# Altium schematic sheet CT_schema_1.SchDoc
size 562 x 511 mm
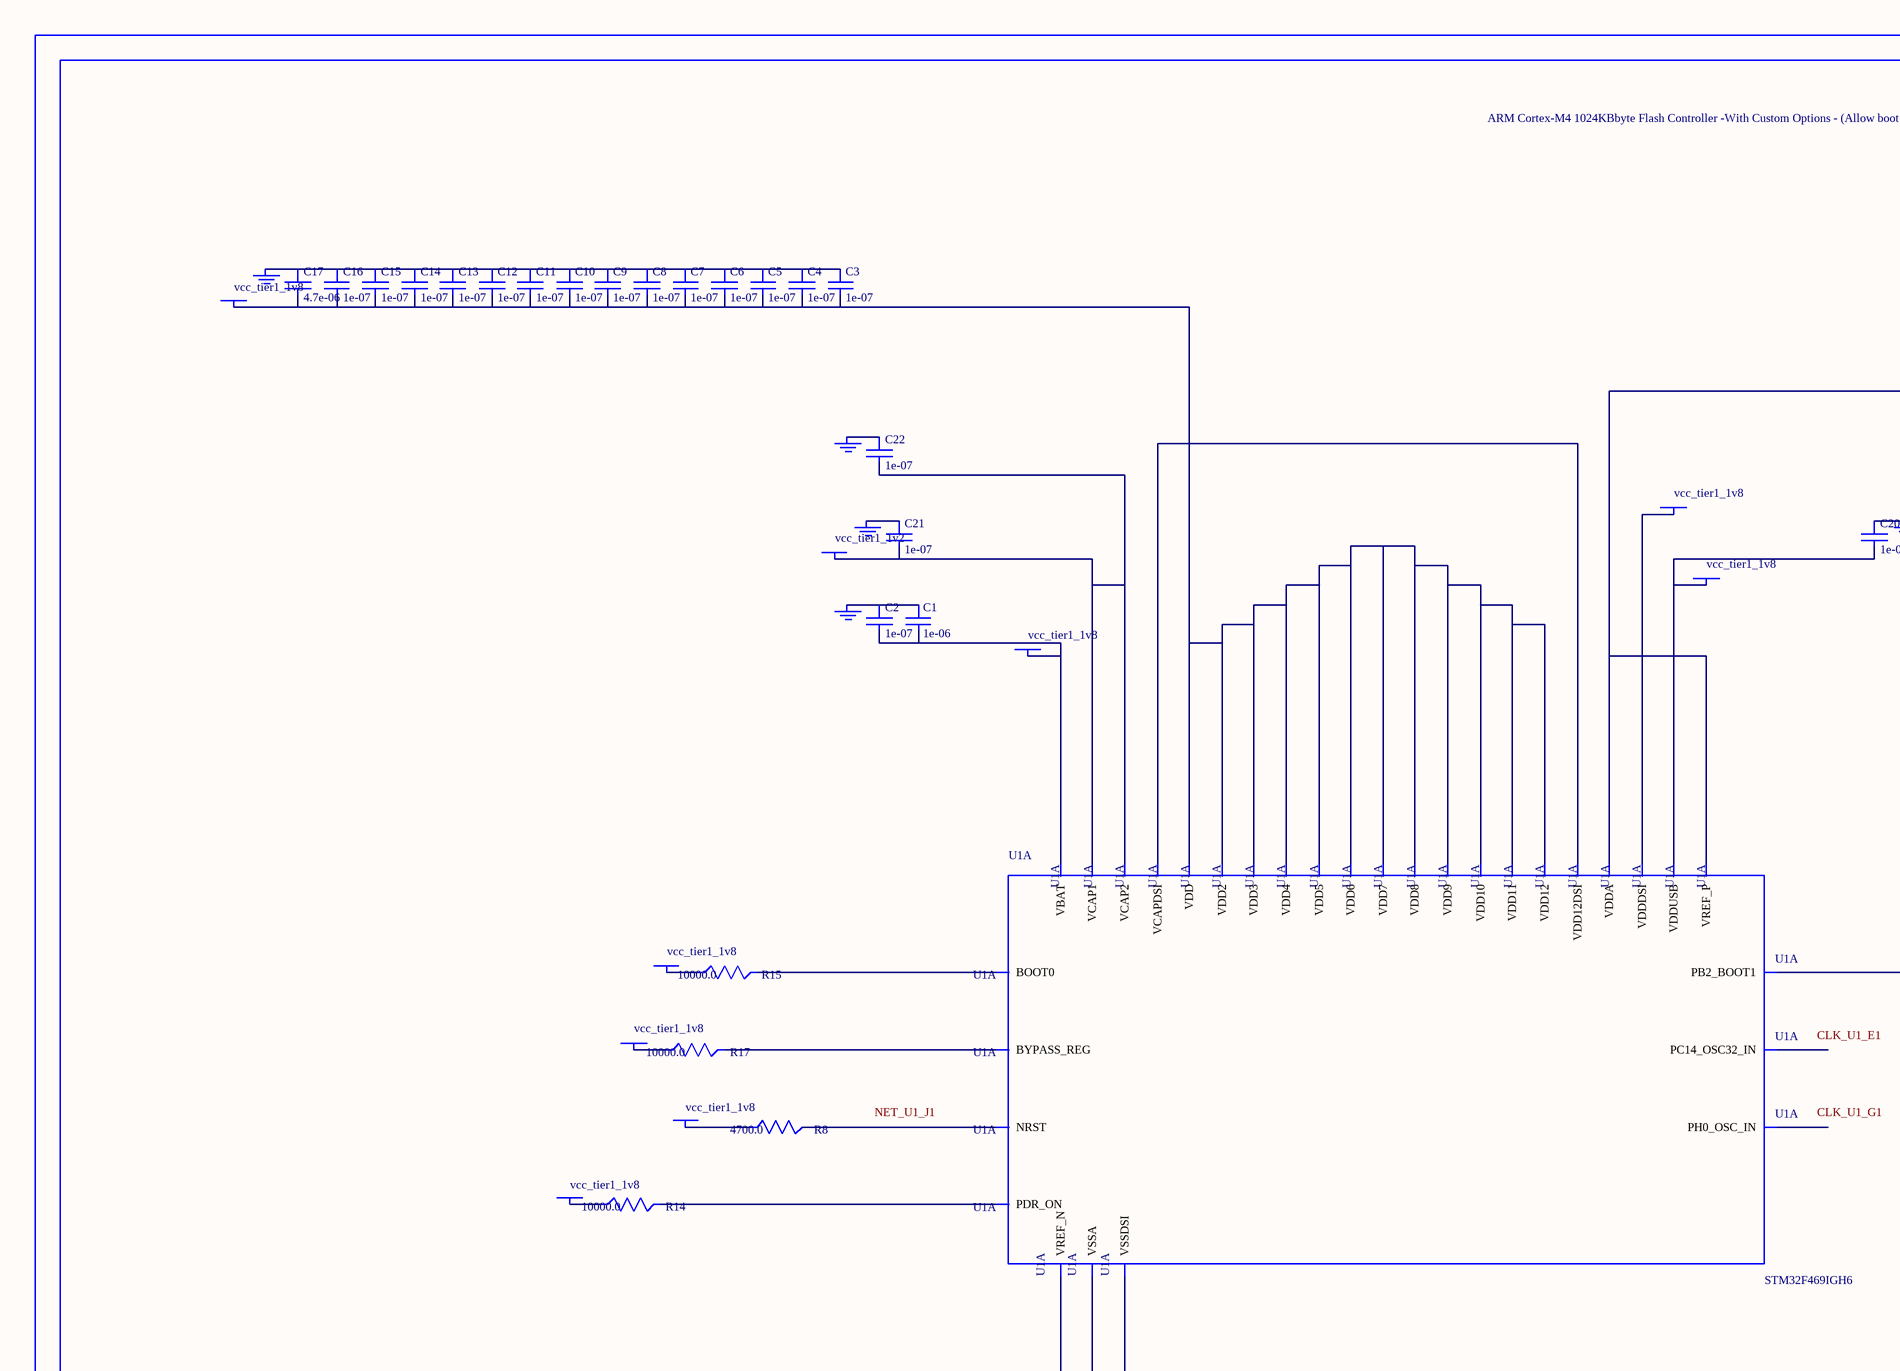
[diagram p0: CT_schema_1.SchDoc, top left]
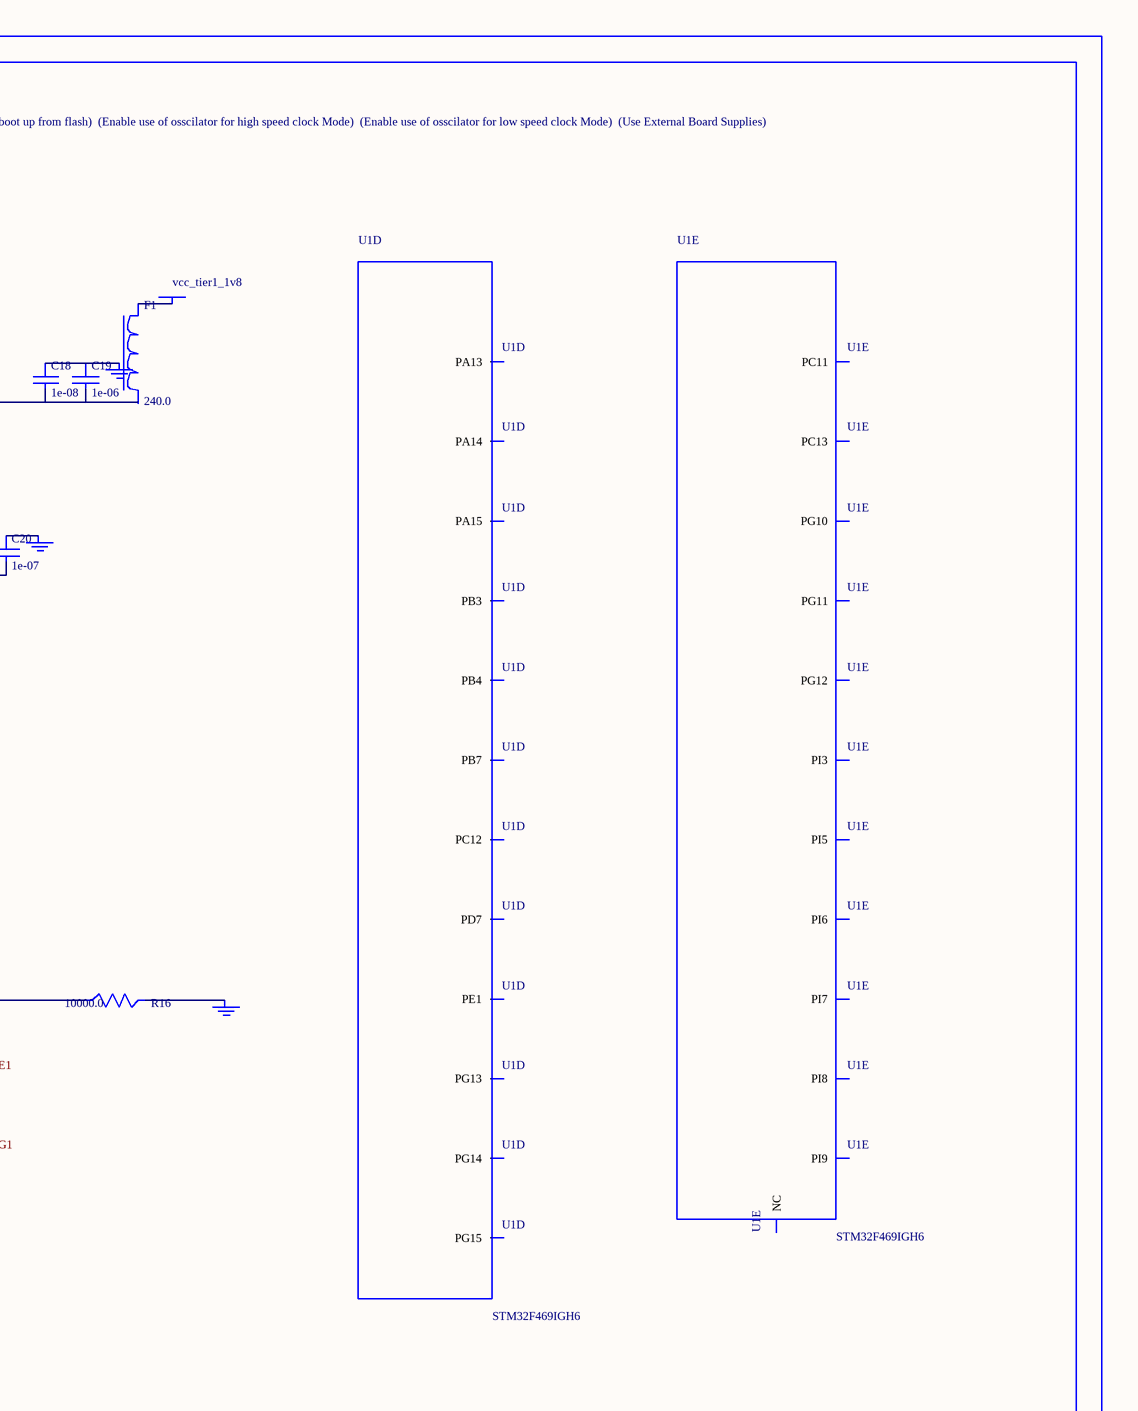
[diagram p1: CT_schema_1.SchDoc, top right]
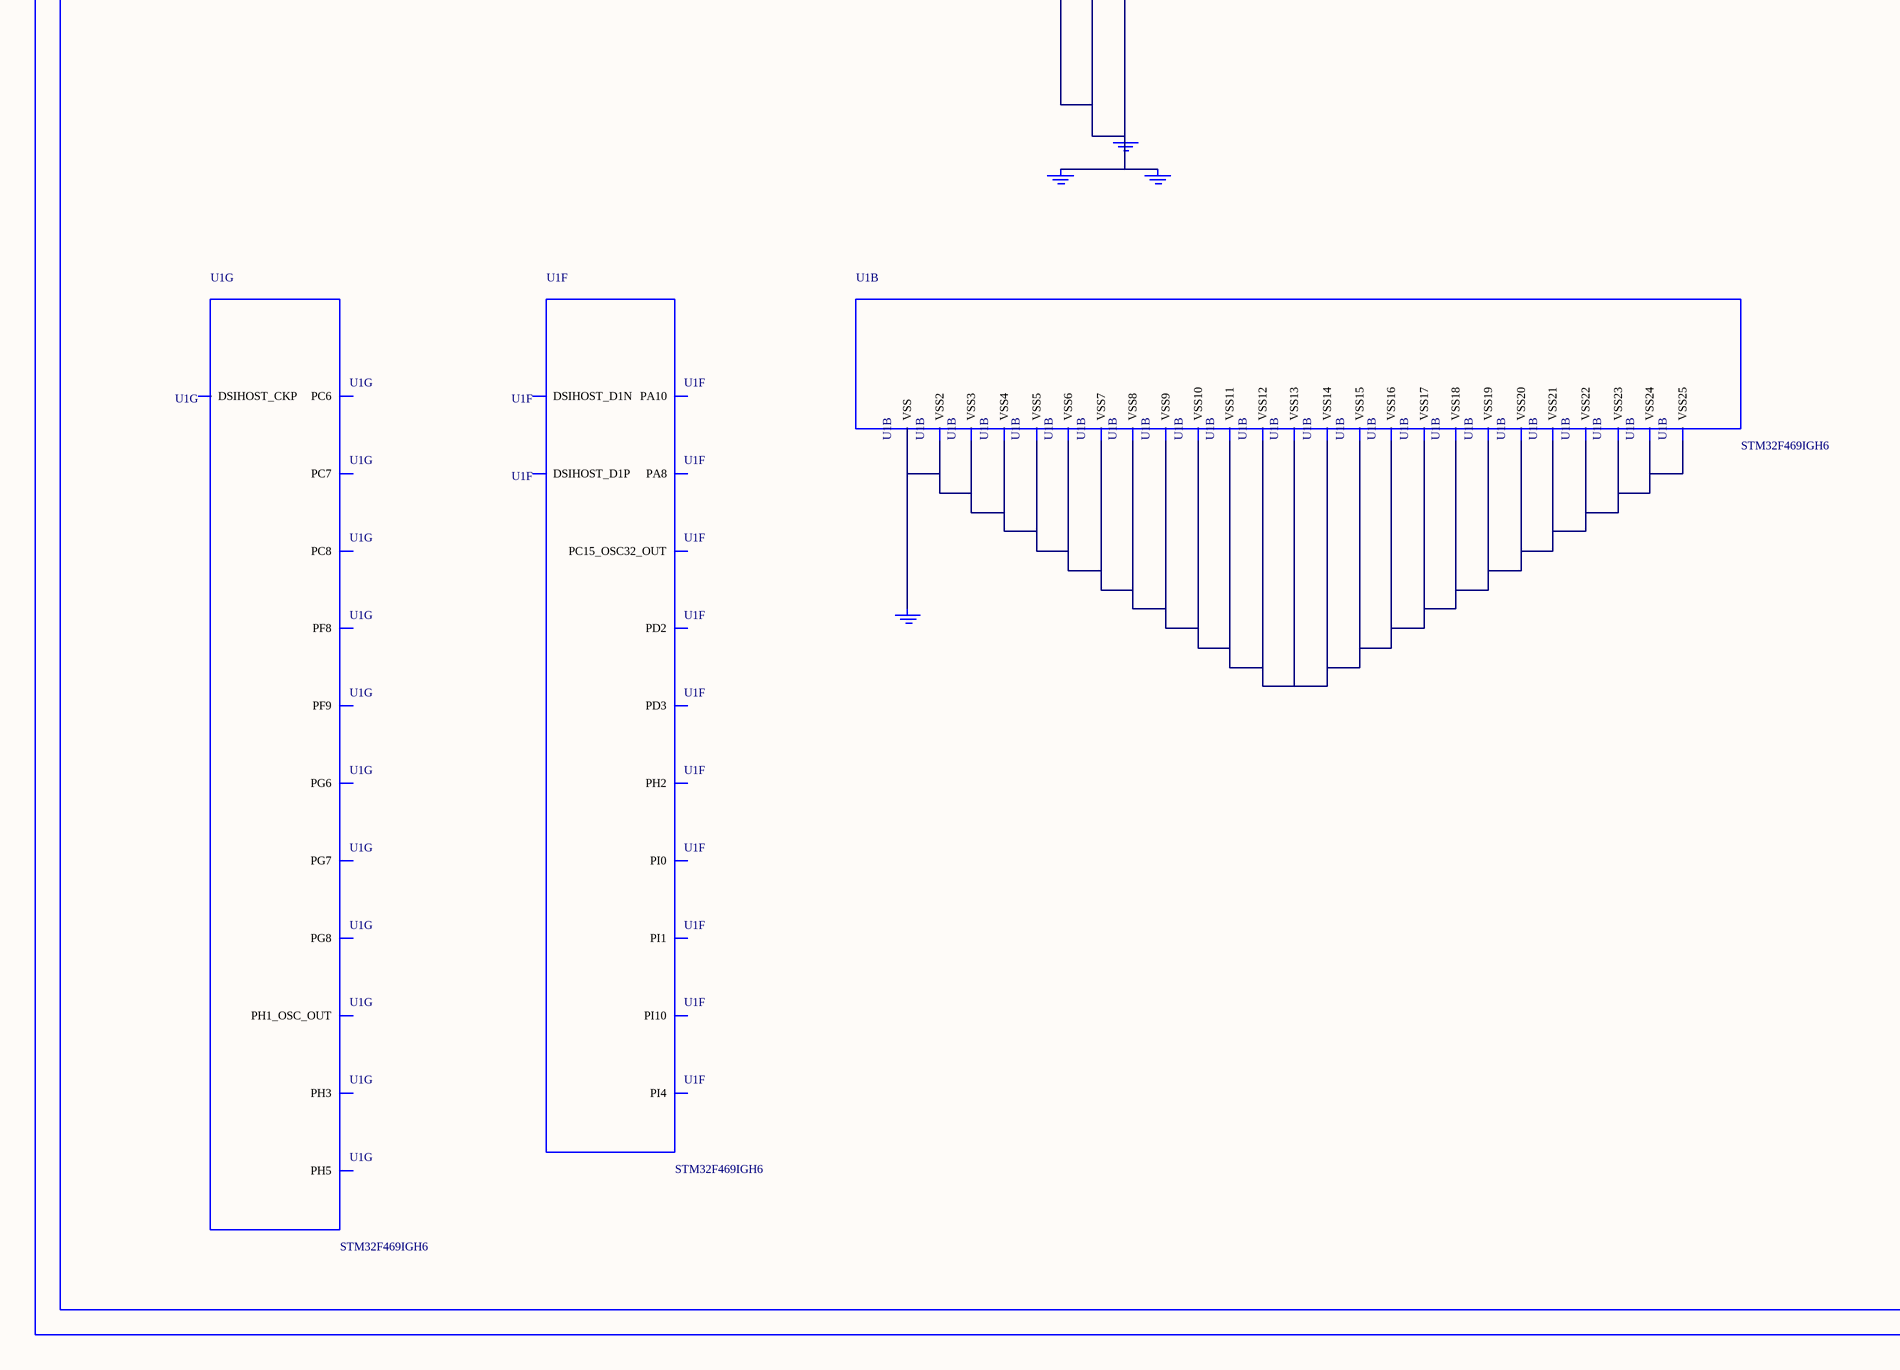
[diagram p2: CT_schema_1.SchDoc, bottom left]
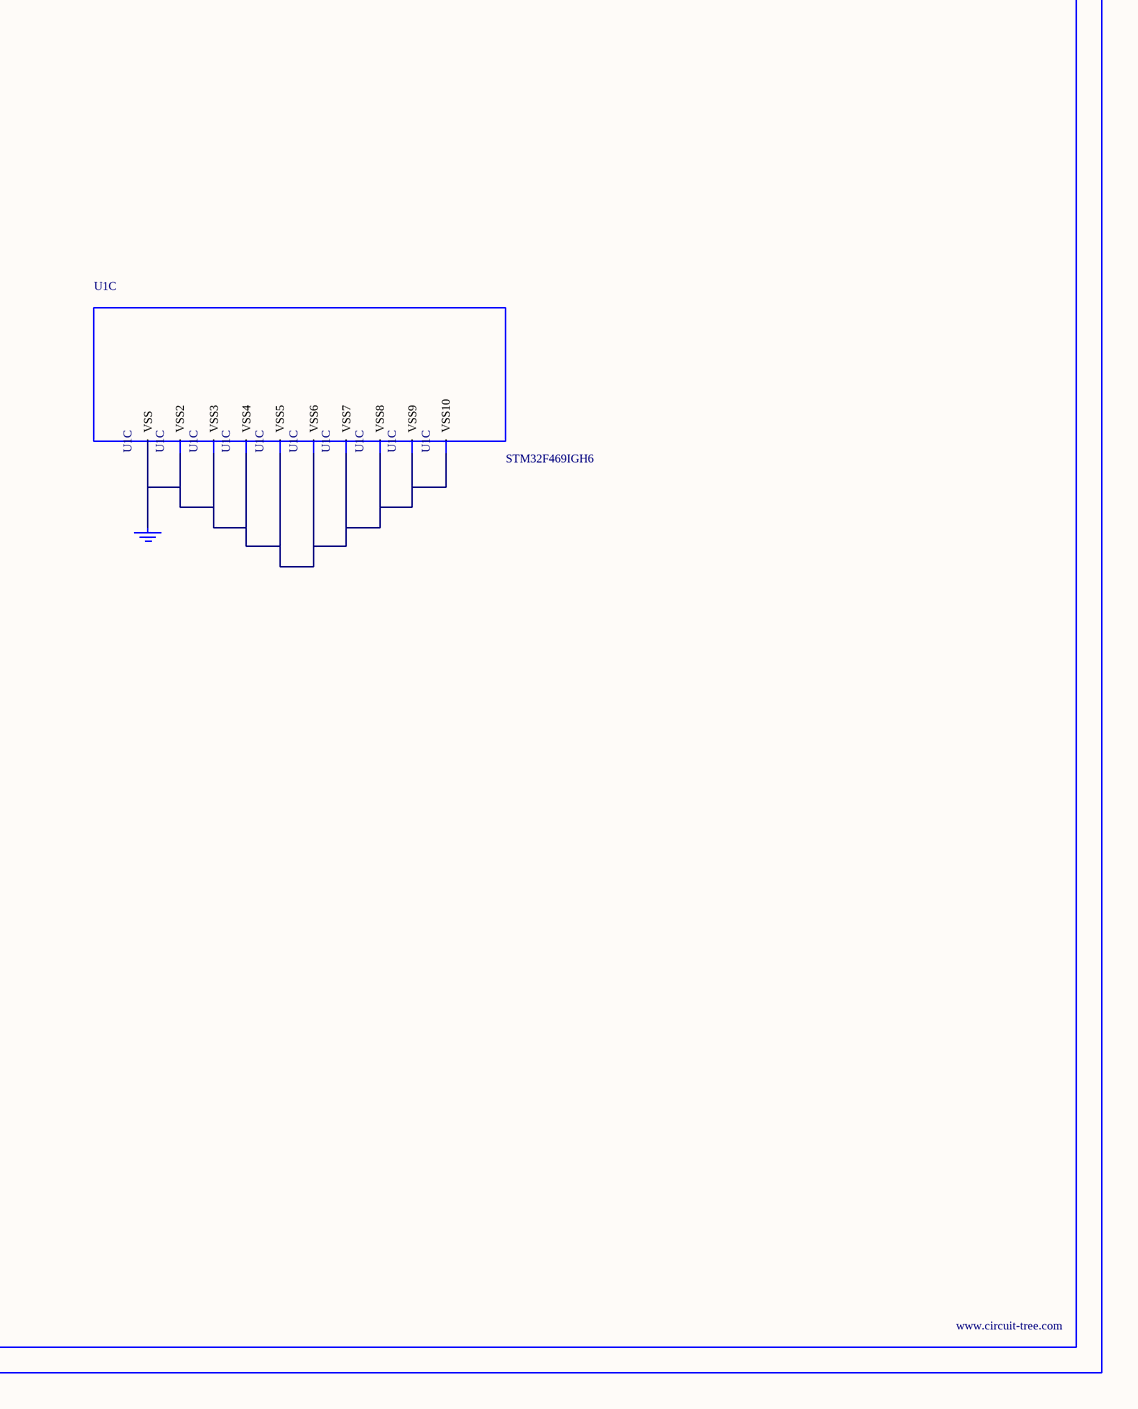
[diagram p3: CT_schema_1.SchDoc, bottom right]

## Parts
BORDER0  (no value)
C1  1e-06  [C0603]
C2  1e-07  [C0603]
C3  1e-07  [C0603]
C4  1e-07  [C0603]
C5  1e-07  [C0603]
C6  1e-07  [C0603]
C7  1e-07  [C0603]
C8  1e-07  [C0603]
C9  1e-07  [C0603]
C10  1e-07  [C0603]
C11  1e-07  [C0603]
C12  1e-07  [C0603]
C13  1e-07  [C0603]
C14  1e-07  [C0603]
C15  1e-07  [C0603]
C16  1e-07  [C0603]
C17  4.7e-06  [C0603]
C18  1e-08  [C0603]
C19  1e-06  [C0603]
C20  1e-07  [C0603]
C21  1e-07  [C0603]
C22  1e-07  [C0603]
F1  240.0  [L0603]
GND_INSTANCE_0_0  (no value)
GND_INSTANCE_0_1  (no value)
GND_INSTANCE_0_2  (no value)
GND_INSTANCE_0_3  (no value)
GND_INSTANCE_0_4  (no value)
GND_INSTANCE_0_5  (no value)
GND_INSTANCE_0_6  (no value)
GND_INSTANCE_0_7  (no value)
GND_INSTANCE_0_8  (no value)
GND_INSTANCE_0_9  (no value)
GND_INSTANCE_0_10  (no value)
GND_INSTANCE_0_11  (no value)
POWER_INSTANCE_0_0  vcc_tier1_1v8
POWER_INSTANCE_0_1  vcc_tier1_1v8
POWER_INSTANCE_0_2  vcc_tier1_1v8
POWER_INSTANCE_0_3  vcc_tier1_1v8
POWER_INSTANCE_0_4  vcc_tier1_1v8
POWER_INSTANCE_0_5  vcc_tier1_1v8
POWER_INSTANCE_0_6  vcc_tier1_1v8
POWER_INSTANCE_0_7  vcc_tier1_1v2
POWER_INSTANCE_0_8  vcc_tier1_1v8
POWER_INSTANCE_0_9  vcc_tier1_1v8
R8  4700.0  [R0603]
R14  10000.0  [R0603]
R15  10000.0  [R0603]
R16  10000.0  [R0603]
R17  10000.0  [R0603]
U1  STM32F469IGH6  [UFBGA176]  (parts A,B,C,D,E,F,G of 16)

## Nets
NetC1_1: C1.1 C2.1 GND_INSTANCE_0_0.0(GND)
NetC1_2: C1.2 C2.2 POWER_INSTANCE_0_0.0(PWR) U1.C1(VBAT)
NetC3_1: C3.1 C4.1 C5.1 C6.1 C7.1 C8.1 C9.1 C10.1 C11.1 C12.1 C13.1 C14.1 C15.1 C16.1 C17.1 GND_INSTANCE_0_2.0(GND)
NetC3_2: C3.2 C4.2 C5.2 C6.2 C7.2 C8.2 C9.2 C10.2 C11.2 C12.2 C13.2 C14.2 C15.2 C16.2 C17.2 POWER_INSTANCE_0_2.0(PWR) U1.C5(VDD) U1.C7(VDD2) U1.C8(VDD3) U1.C9(VDD4) U1.F3(VDD5) U1.G3(VDD7) U1.G13(VDD6) U1.J13(VDD8) U1.K4(VDD9) U1.N8(VDD11) U1.N9(VDD12) U1.N10(VDD10)
NetC18_1: C18.1 C19.1 GND_INSTANCE_0_1.0(GND)
NetC18_2: C18.2 C19.2 U1.P1(VREF_P) U1.R1(VDDA)
NetC20_1: C20.1 GND_INSTANCE_0_3.0(GND)
NetC20_2: C20.2 POWER_INSTANCE_0_4.0(PWR) U1.H13(VDDUSB)
NetC21_1: C21.1 GND_INSTANCE_0_5.0(GND)
NetC21_2: C21.2 C22.2 POWER_INSTANCE_0_7.0(PWR) U1.F13(VCAP2) U1.M10(VCAP1)
NetC22_1: C22.1 GND_INSTANCE_0_6.0(GND)
NetF1_1: F1.1 POWER_INSTANCE_0_1.0(PWR)
NetGND_INSTANCE_0_4_0: GND_INSTANCE_0_4.0(GND) R16.2
NetGND_INSTANCE_0_7_0: GND_INSTANCE_0_7.0(GND) GND_INSTANCE_0_8.0(GND) GND_INSTANCE_0_9.0(GND) U1.H12(VSSDSI) U1.M1(VSSA) U1.N1(VREF_N)
NetGND_INSTANCE_0_10_0: GND_INSTANCE_0_10.0(GND) U1.D5(VSS) U1.D7(VSS2) U1.D8(VSS3) U1.D9(VSS4) U1.F2(VSS7) U1.F6(VSS8) U1.F7(VSS9) U1.F8(VSS10) U1.F9(VSS11) U1.F10(VSS5) U1.F12(VSS6) U1.G2(VSS14) U1.G6(VSS15) U1.G7(VSS16) U1.G8(VSS17) U1.G9(VSS18) U1.G10(VSS12) U1.G12(VSS13) U1.H6(VSS20) U1.H7(VSS21) U1.H8(VSS22) U1.H9(VSS23) U1.H10(VSS19) U1.J6(VSS25) U1.J10(VSS24)
NetGND_INSTANCE_0_11_0: GND_INSTANCE_0_11.0(GND) U1.J7(VSS) U1.J8(VSS2) U1.J9(VSS3) U1.K6(VSS5) U1.K7(VSS6) U1.K8(VSS7) U1.K9(VSS8) U1.K10(VSS4) U1.M8(VSS9) U1.M9(VSS10)
NetPOWER_INSTANCE_0_3_0: POWER_INSTANCE_0_3.0(PWR) R14.1
NetPOWER_INSTANCE_0_5_0: POWER_INSTANCE_0_5.0(PWR) R15.1
NetPOWER_INSTANCE_0_6_0: POWER_INSTANCE_0_6.0(PWR) R17.1
NetPOWER_INSTANCE_0_8_0: POWER_INSTANCE_0_8.0(PWR) U1.J12(VDDDSI)
NetPOWER_INSTANCE_0_9_0: POWER_INSTANCE_0_9.0(PWR) R8.1
NetR8_2: R8.2 U1.J1(NRST)
NetR14_2: R14.2 U1.C6(PDR_ON)
NetR15_2: R15.2 U1.D6(BOOT0)
NetR16_1: R16.1 U1.M6(PB2_BOOT1)
NetR17_2: R17.2 U1.L4(BYPASS_REG)
NetU1_D13: U1.D13(VDD12DSI) U1.K12(VCAPDSI)

Not connected (* = marked no-connect by the designer): F1 2; U1 A3(PE1) A7(PG14) A8(PG13) A9(PB4) A10(PB3) A11(PD7) A12(PC12) A13(PA15) A14(PA14) A15(PA13) B5(PB7) B7(PG15) B8(PG12) B9(PG11) B10(PG10) B13(PC11) C2(PI7) C3(PI6) C4(PI5) C13(PI3) C14(NC) D1(PC13) D2(PI8) D3(PI9) D4(PI4) D11(PD3) D12(PD2) D14(PI1) D15(PA10) E1(PC14_OSC32_IN) E3(PI10) E12(DSIHOST_D1P) E13(DSIHOST_D1N) E14(PI0) F1(PC15_OSC32_OUT) F4(PH2) F15(PA8) G1(PH0_OSC_IN) G4(PH3) G14(PC8) G15(PC7) H1(PH1_OSC_OUT) H14(PG8) H15(PC6) J4(PH5) J14(PG7) J15(PG6) L2(PF9) L3(PF8) L12(DSIHOST_CKP)

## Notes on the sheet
- Labels drawn without touching a wire or pin: CLK_U1_E1, CLK_U1_G1, NET_U1_J1

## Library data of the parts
BORDER0 = BORDER_PAGE0
C1 C19 = C0603C105K3RACTU
C2-C16 C20-C22 = 06035C104K4Z2A
C17 = GRM188R6YA475KE15D
C18 = 06035C103K4Z2A
F1 = Z0603C241ASMST
GND_INSTANCE_0_0-GND_INSTANCE_0_11 = GND
POWER_INSTANCE_0_0-POWER_INSTANCE_0_9 = PWR
R8 = RC0603JR-074K7L
R14-R17 = RC0603JR-0710KL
